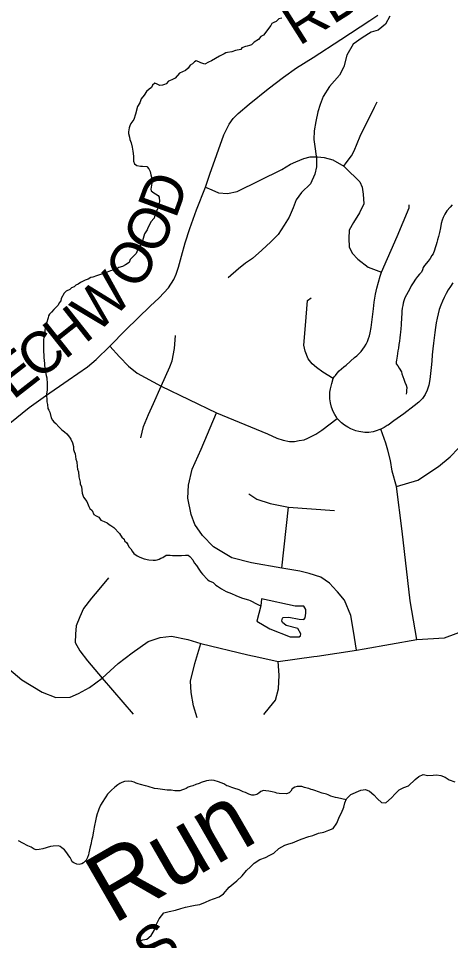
# Model space of a CAD drawing. Extents: x 0 to 34, y 0 to 22.
# Drawn here: x 6.521 to 6.817, y 17.744 to 18.376 of the extents above; entities that cross this region are included whole.
import ezdxf

# ---------------------------------------------------------------- set-up
doc = ezdxf.new("R2010")
doc.units = 0
for name, color, linetype in [('GM_X_County_Road', 7, 'Continuous'), ('GM_X_County_Road_Text', 7, 'Continuous'), ('GM_X_Minor_Lake', 7, 'Continuous'), ('GM_X_Minor_River', 7, 'Continuous'), ('GM_X_Minor_River_Text', 7, 'Continuous'), ('GM_X_Township_Road', 7, 'Continuous'), ('GM_X_Township_Road_Text', 7, 'Continuous')]:
    doc.layers.add(name, color=color, linetype=linetype)

msp = doc.modelspace()

# ---------------------------------------------------------------- linework, layer by layer
at = {"layer": 'GM_X_County_Road'}
msp.add_lwpolyline([(6.51493, 18.09881), (6.52823, 18.10962), (6.5394, 18.11761), (6.55486, 18.12827), (6.5682, 18.13748), (6.57406, 18.1425), (6.58342, 18.15154), (6.59459, 18.16279), (6.61122, 18.17904), (6.61746, 18.18472), (6.62369, 18.19151), (6.62733, 18.19732), (6.62906, 18.20102), (6.63053, 18.20577), (6.63274, 18.21337), (6.63519, 18.22251), (6.63835, 18.23227), (6.64303, 18.24515), (6.6491, 18.26068), (6.65215, 18.2695), (6.66179, 18.29652), (6.66541, 18.30386), (6.66817, 18.30761), (6.67154, 18.31102), (6.67912, 18.31746), (6.69226, 18.32802), (6.70262, 18.33596), (6.71171, 18.34236), (6.72311, 18.34954), (6.74197, 18.36181), (6.76197, 18.37478), (6.76751, 18.37848)], dxfattribs=at)
at = {"layer": 'GM_X_Minor_Lake'}
for points in [[(6.71064, 17.97344), (6.68757, 17.97848), (6.68724, 17.97355)], [(6.68724, 17.97355), (6.68441, 17.96315), (6.69341, 17.95784), (6.70736, 17.95242), (6.71344, 17.95248), (6.7144, 17.95303), (6.71462, 17.95455), (6.71261, 17.9582), (6.70448, 17.96027), (6.70205, 17.96222), (6.70151, 17.96337), (6.70212, 17.96525), (6.7025, 17.96563), (6.70631, 17.96593), (6.7135, 17.96445), (6.71673, 17.96438), (6.71751, 17.96551), (6.71814, 17.96854), (6.71801, 17.9712), (6.71672, 17.97331), (6.71064, 17.97344)]]:
    msp.add_lwpolyline(points, dxfattribs=at)
at = {"layer": 'GM_X_Minor_River'}
for points in [[(6.70166, 18.37648), (6.69956, 18.37597), (6.69761, 18.37412), (6.69608, 18.3734), (6.69473, 18.37287), (6.69413, 18.37137), (6.69236, 18.36933), (6.69059, 18.36691), (6.68902, 18.36486), (6.6871, 18.36377), (6.68553, 18.36192), (6.68263, 18.3601), (6.68069, 18.35825), (6.67934, 18.35772), (6.67781, 18.35719), (6.67667, 18.35703), (6.67418, 18.35614), (6.67339, 18.35503), (6.66976, 18.35436), (6.66727, 18.35348), (6.66422, 18.35299), (6.66307, 18.35264), (6.66192, 18.35191), (6.65884, 18.35047), (6.65325, 18.34721), (6.65133, 18.34631), (6.64863, 18.34486), (6.646, 18.34588), (6.64469, 18.34648), (6.6428, 18.3471), (6.64165, 18.34656), (6.64028, 18.34508), (6.63874, 18.34417), (6.63717, 18.34213), (6.63542, 18.34065), (6.63138, 18.33867), (6.62826, 18.33534), (6.62614, 18.33426), (6.62384, 18.33318), (6.62228, 18.33151), (6.62112, 18.33097), (6.61959, 18.33045), (6.61788, 18.3303), (6.616, 18.3313), (6.6145, 18.33191), (6.61276, 18.33062), (6.61214, 18.32893), (6.6106, 18.32783), (6.60866, 18.32618), (6.60707, 18.32375), (6.60511, 18.32115), (6.60451, 18.31984), (6.60409, 18.31833), (6.60251, 18.3159), (6.60123, 18.31063), (6.6, 18.30706), (6.59784, 18.30427), (6.59723, 18.30257), (6.59682, 18.30126), (6.59637, 18.29861), (6.59634, 18.29729), (6.59703, 18.2948), (6.59718, 18.29328), (6.59808, 18.29098), (6.59876, 18.28812), (6.59926, 18.28526), (6.59974, 18.28183), (6.59969, 18.27993), (6.59985, 18.27841), (6.60037, 18.2765), (6.60205, 18.27551), (6.60451, 18.27507), (6.60584, 18.27503)], [(6.77562, 18.37773), (6.77265, 18.37227), (6.76763, 18.36819), (6.76286, 18.36676), (6.7567, 18.36289), (6.75053, 18.35863), (6.7462, 18.35111), (6.74414, 18.34317), (6.74117, 18.33733), (6.73417, 18.32967), (6.73004, 18.32272), (6.72784, 18.31725), (6.72622, 18.31234), (6.72494, 18.30571), (6.72386, 18.29926), (6.72354, 18.29318), (6.72455, 18.28689), (6.72536, 18.28003), (6.72525, 18.27452), (6.72419, 18.26941), (6.72121, 18.26281), (6.715, 18.25684), (6.71149, 18.25197), (6.70928, 18.2465), (6.70649, 18.24009), (6.70315, 18.23445), (6.69903, 18.22807), (6.69398, 18.22303), (6.68779, 18.21745), (6.68141, 18.21168), (6.67659, 18.20854), (6.67177, 18.20464), (6.6648, 18.1985)], [(6.60584, 18.27503), (6.60887, 18.27476), (6.61035, 18.27321), (6.61125, 18.27129), (6.61176, 18.269), (6.61227, 18.26652), (6.6126, 18.26461), (6.6117, 18.25932), (6.61186, 18.25818), (6.61373, 18.2568), (6.61485, 18.25602), (6.61672, 18.25483), (6.61726, 18.25368), (6.61757, 18.25082), (6.61714, 18.24894), (6.6167, 18.24667), (6.6159, 18.24499), (6.6147, 18.24255), (6.61385, 18.23935), (6.6117, 18.23694), (6.6107, 18.23469), (6.60951, 18.23263), (6.60909, 18.23131), (6.60731, 18.22852), (6.60544, 18.22211), (6.60406, 18.22006), (6.60268, 18.2182), (6.60206, 18.21632), (6.60166, 18.21519), (6.60048, 18.2139), (6.59932, 18.21279), (6.59738, 18.21113), (6.59675, 18.20906), (6.59424, 18.20742), (6.59231, 18.20633), (6.58963, 18.20545), (6.58829, 18.20473), (6.58675, 18.20401), (6.58388, 18.20333), (6.58158, 18.20244), (6.57908, 18.20137), (6.57717, 18.20085), (6.57564, 18.20032), (6.5743, 18.19979), (6.57181, 18.1989), (6.57047, 18.19875), (6.56854, 18.19747), (6.56662, 18.19676), (6.56336, 18.19533), (6.56181, 18.19404), (6.56008, 18.19352), (6.55911, 18.1924), (6.55719, 18.1917), (6.55602, 18.1904), (6.55352, 18.18933), (6.55216, 18.18803), (6.55016, 18.18429), (6.54993, 18.18278), (6.54876, 18.18129), (6.54796, 18.1798), (6.54601, 18.17776), (6.54503, 18.17665), (6.54347, 18.17498), (6.5421, 18.1735), (6.54132, 18.17238), (6.54109, 18.17106), (6.54005, 18.16729), (6.53898, 18.16258), (6.53895, 18.16144), (6.53852, 18.15956), (6.53829, 18.15785), (6.53805, 18.15596), (6.53794, 18.15179), (6.53802, 18.14724), (6.53818, 18.14609), (6.53832, 18.14438), (6.53844, 18.14135), (6.5386, 18.1402), (6.53875, 18.13887), (6.53888, 18.1364), (6.53903, 18.13488), (6.5399, 18.13163), (6.54023, 18.12992), (6.5402, 18.12859), (6.54055, 18.12725), (6.54041, 18.12175), (6.54014, 18.11873), (6.5401, 18.11721), (6.54025, 18.11569), (6.54038, 18.11341), (6.54072, 18.11169), (6.54103, 18.10884), (6.54157, 18.10769), (6.54229, 18.10634), (6.54334, 18.10252), (6.54425, 18.10098), (6.54517, 18.09981), (6.54647, 18.09864), (6.5485, 18.09631), (6.55054, 18.09436), (6.5524, 18.09299)], [(6.81843, 18.2486), (6.81706, 18.24693), (6.81472, 18.24434), (6.81412, 18.24321), (6.81333, 18.24209), (6.81232, 18.23984), (6.81152, 18.23797), (6.81089, 18.23571), (6.81043, 18.23269), (6.80978, 18.22948), (6.80914, 18.22684), (6.80852, 18.22458), (6.8079, 18.2227), (6.80748, 18.221), (6.80686, 18.21912), (6.80625, 18.21743), (6.80542, 18.21498), (6.80463, 18.21368), (6.80345, 18.21181), (6.80207, 18.20995), (6.79952, 18.20698), (6.79854, 18.20549), (6.79812, 18.20398), (6.79732, 18.2023), (6.79614, 18.201), (6.79458, 18.19933), (6.79339, 18.19747), (6.79181, 18.19504), (6.79043, 18.19299), (6.78943, 18.19093), (6.78824, 18.18888), (6.78604, 18.18476), (6.78523, 18.18269), (6.78481, 18.18119), (6.78458, 18.17949), (6.78415, 18.1776), (6.78392, 18.17571), (6.78386, 18.17362), (6.78362, 18.17154), (6.78348, 18.16624), (6.78323, 18.16359), (6.78298, 18.16132), (6.78274, 18.15943), (6.7825, 18.15734), (6.78225, 18.15507), (6.78181, 18.15281), (6.78156, 18.15035), (6.78113, 18.14846), (6.78089, 18.14657), (6.78066, 18.14487), (6.78043, 18.14336), (6.78021, 18.14204), (6.77999, 18.14091), (6.78015, 18.13957), (6.78125, 18.13803), (6.78216, 18.13649), (6.78361, 18.13398), (6.78396, 18.13265), (6.78467, 18.13073), (6.78539, 18.129), (6.78609, 18.1269), (6.7868, 18.12498), (6.78733, 18.12326), (6.78709, 18.12118), (6.78706, 18.12004), (6.78683, 18.11872)], [(6.5524, 18.09299), (6.55407, 18.09142), (6.55572, 18.08929), (6.55664, 18.08794), (6.5579, 18.08525), (6.5586, 18.08277), (6.55854, 18.08068), (6.55908, 18.07953), (6.55961, 18.07781), (6.56028, 18.07419), (6.5608, 18.07228), (6.5611, 18.06904), (6.56143, 18.06733), (6.56195, 18.06542), (6.56225, 18.062), (6.56277, 18.06027), (6.5631, 18.05837), (6.56326, 18.05723), (6.56398, 18.05531), (6.56462, 18.05093), (6.5655, 18.04806), (6.56771, 18.04516), (6.56914, 18.04171), (6.56986, 18.04036), (6.57135, 18.03899), (6.57261, 18.0363), (6.5741, 18.03531), (6.57598, 18.03432), (6.57745, 18.03238), (6.57951, 18.03138), (6.58177, 18.03056), (6.58307, 18.02939), (6.58419, 18.02879), (6.58624, 18.02722), (6.59013, 18.02313), (6.59086, 18.02198), (6.59177, 18.02081), (6.59344, 18.01925), (6.59361, 18.01811), (6.59509, 18.01674), (6.59582, 18.01559), (6.59654, 18.01405), (6.59784, 18.01269), (6.59875, 18.01115), (6.60004, 18.0096), (6.60227, 18.00783), (6.60415, 18.00702), (6.60716, 18.0058), (6.61018, 18.00516), (6.61321, 18.00489), (6.61492, 18.00503), (6.61607, 18.00519), (6.61741, 18.00573), (6.61856, 18.00627), (6.61991, 18.0068), (6.62222, 18.00826), (6.62356, 18.00841), (6.62488, 18.00838), (6.62659, 18.00814), (6.62981, 18.00806), (6.63266, 18.00817), (6.63552, 18.00848), (6.63723, 18.00843), (6.63834, 18.00745), (6.64056, 18.00512), (6.64146, 18.00301), (6.64293, 18.00126), (6.64458, 17.99875), (6.64586, 17.99682), (6.64715, 17.99527), (6.65048, 17.99177), (6.65178, 17.99079), (6.65441, 17.98958), (6.65627, 17.98782), (6.65739, 17.98723), (6.66019, 17.98526), (6.66169, 17.98446), (6.66337, 17.98347), (6.66694, 17.98204), (6.66995, 17.98083), (6.67277, 17.97962), (6.67446, 17.979), (6.67861, 17.97776), (6.67974, 17.97735), (6.68124, 17.97655), (6.6833, 17.97555), (6.68461, 17.97475), (6.68611, 17.97414), (6.68724, 17.97355)], [(6.60245, 17.74361), (6.60607, 17.74469), (6.60892, 17.74521), (6.61181, 17.74763), (6.61396, 17.7512), (6.61536, 17.75498), (6.61733, 17.75913), (6.62063, 17.76325), (6.62425, 17.76414), (6.62862, 17.76501), (6.63225, 17.76609), (6.63549, 17.76717), (6.63968, 17.76805), (6.64215, 17.76839), (6.64538, 17.7689), (6.6492, 17.77055), (6.65207, 17.77183), (6.65474, 17.77273), (6.65856, 17.77419), (6.66163, 17.77622), (6.6655, 17.78072), (6.6682, 17.78314), (6.67071, 17.78519), (6.67437, 17.78854), (6.67728, 17.79229), (6.67998, 17.79472), (6.68268, 17.79733), (6.68652, 17.79974), (6.69034, 17.80119), (6.6934, 17.80266), (6.69608, 17.80413), (6.69955, 17.8073), (6.70357, 17.80951), (6.70644, 17.8106), (6.70891, 17.81113), (6.71216, 17.81259), (6.71483, 17.81369), (6.72018, 17.8155), (6.72284, 17.81621), (6.72667, 17.81786), (6.73028, 17.81855), (6.73372, 17.81982), (6.73678, 17.8211), (6.73931, 17.82467), (6.74109, 17.8292), (6.74247, 17.83164), (6.74405, 17.83561), (6.74487, 17.83863), (6.74605, 17.84127), (6.74895, 17.84426), (6.75583, 17.84718), (6.75906, 17.8477), (6.7617, 17.84651), (6.76468, 17.84399), (6.76729, 17.84129), (6.7699, 17.83877), (6.77293, 17.83872), (6.77679, 17.84207), (6.7793, 17.84469), (6.782, 17.84749), (6.78526, 17.84915), (6.7885, 17.85023), (6.79313, 17.85471), (6.79563, 17.85657), (6.7985, 17.85804), (6.80172, 17.85742), (6.80532, 17.85754), (6.80779, 17.85769), (6.81063, 17.85726), (6.81364, 17.85626), (6.81645, 17.85431), (6.82022, 17.85292)], [(6.74577, 17.84063), (6.73973, 17.84203), (6.7384, 17.84226), (6.7367, 17.84268), (6.7352, 17.8431), (6.73332, 17.8441), (6.73219, 17.84451), (6.72936, 17.84515), (6.72428, 17.84699), (6.72277, 17.84741), (6.72164, 17.84782), (6.72014, 17.84843), (6.719, 17.84865), (6.71712, 17.84907), (6.71523, 17.84969), (6.71201, 17.84978), (6.71048, 17.84944), (6.70874, 17.84816), (6.70775, 17.84666), (6.70658, 17.84537), (6.70466, 17.84485), (6.69973, 17.84498), (6.69822, 17.84521), (6.69709, 17.84561), (6.69501, 17.84605), (6.69388, 17.84627), (6.69256, 17.84668), (6.69066, 17.84692), (6.68896, 17.84697), (6.68704, 17.84645), (6.68569, 17.84534), (6.68433, 17.84443), (6.68261, 17.84391), (6.6809, 17.84395), (6.67902, 17.84457), (6.67658, 17.84558), (6.67507, 17.84619), (6.67226, 17.84759), (6.66868, 17.84863), (6.66736, 17.84905), (6.66492, 17.85006), (6.66378, 17.85028), (6.66173, 17.85166), (6.65816, 17.85308), (6.65514, 17.85392), (6.65306, 17.85416), (6.64982, 17.85368), (6.64618, 17.85245), (6.64483, 17.85191), (6.64254, 17.85122), (6.64042, 17.85032), (6.6387, 17.8498), (6.63736, 17.84927), (6.63601, 17.84854), (6.63467, 17.84801), (6.63332, 17.84747), (6.6316, 17.84676), (6.62818, 17.84685), (6.62553, 17.8473), (6.62288, 17.84737), (6.61644, 17.84811), (6.61417, 17.84854), (6.60984, 17.8498), (6.60795, 17.85022), (6.60455, 17.85107), (6.60286, 17.85169), (6.60154, 17.8521), (6.60022, 17.8527), (6.59852, 17.85313), (6.59626, 17.85357), (6.59359, 17.85326), (6.59167, 17.85255), (6.59033, 17.85182), (6.58897, 17.85091), (6.58685, 17.84945), (6.58432, 17.84705), (6.58197, 17.84445), (6.58079, 17.84278), (6.5798, 17.84129), (6.57862, 17.83942), (6.57722, 17.83699), (6.57602, 17.83436), (6.57541, 17.83286), (6.57479, 17.83098), (6.57416, 17.82853), (6.57372, 17.82627), (6.57307, 17.82306), (6.57285, 17.82193), (6.5724, 17.81909), (6.57218, 17.81796), (6.57154, 17.81513), (6.57113, 17.81381), (6.57046, 17.81004), (6.57004, 17.80853), (6.56918, 17.80438), (6.56876, 17.80287), (6.56815, 17.80118), (6.56734, 17.79931), (6.56539, 17.79746), (6.56424, 17.79673), (6.56252, 17.7964)], [(6.56252, 17.7964), (6.56082, 17.79663), (6.55875, 17.79745), (6.55763, 17.79823), (6.55709, 17.79939), (6.55618, 17.80112), (6.55545, 17.80227), (6.55399, 17.8044), (6.55233, 17.80634), (6.55065, 17.80771), (6.54935, 17.80869), (6.54822, 17.8091), (6.54461, 17.80901), (6.5427, 17.80868), (6.53753, 17.80711), (6.53505, 17.8066), (6.53296, 17.80647), (6.53164, 17.80688), (6.52959, 17.80826), (6.52733, 17.80908), (6.52377, 17.81088), (6.52077, 17.81248)]]:
    msp.add_lwpolyline(points, dxfattribs=at)
at = {"layer": 'GM_X_Township_Road'}
msp.add_line((6.7015, 17.99956), (6.70606, 18.0412), dxfattribs=at)
for points in [[(6.74411, 18.27502), (6.74564, 18.27725), (6.7494, 18.28217), (6.75128, 18.28554), (6.75541, 18.29546), (6.76513, 18.31537), (6.76702, 18.319)], [(6.6491, 18.26068), (6.65353, 18.25875), (6.65813, 18.25681), (6.66428, 18.25619), (6.67083, 18.25753), (6.70151, 18.27274), (6.70762, 18.27629), (6.71111, 18.27804), (6.71671, 18.28031), (6.72108, 18.28136), (6.72606, 18.28136), (6.73052, 18.28101), (6.73655, 18.27926), (6.74411, 18.27502), (6.74818, 18.27096), (6.75185, 18.26746), (6.75499, 18.26432), (6.75665, 18.26064), (6.75744, 18.25575), (6.75779, 18.24928), (6.75491, 18.24299), (6.75066, 18.23639), (6.74774, 18.2311), (6.74751, 18.22536), (6.74779, 18.21963), (6.7498, 18.21533), (6.75367, 18.21117), (6.76083, 18.20573), (6.77003, 18.20232)], [(6.81904, 18.19496), (6.81737, 18.19263), (6.8158, 18.1902), (6.81435, 18.18769), (6.81369, 18.18638), (6.81302, 18.18508), (6.81178, 18.18241), (6.81066, 18.17964), (6.80966, 18.17677), (6.80884, 18.17379), (6.80814, 18.17078), (6.80756, 18.16762), (6.80704, 18.16439), (6.80655, 18.16101), (6.80609, 18.15744), (6.80566, 18.15369), (6.80524, 18.14975), (6.80482, 18.14564), (6.80444, 18.14137), (6.80403, 18.13703), (6.80358, 18.13279), (6.80308, 18.12875), (6.8024, 18.125), (6.80137, 18.12155), (6.79994, 18.11844), (6.79856, 18.11642), (6.79806, 18.11568), (6.79569, 18.11325), (6.79249, 18.11078), (6.78534, 18.10526), (6.77845, 18.10038), (6.77448, 18.09757), (6.77387, 18.09714), (6.7718, 18.09591), (6.76952, 18.09466), (6.76564, 18.09339), (6.76422, 18.09299), (6.76136, 18.0925), (6.7586, 18.0925), (6.75443, 18.09304), (6.7524, 18.09367), (6.75122, 18.09404), (6.74886, 18.09498), (6.74682, 18.09606), (6.74458, 18.09749), (6.74259, 18.09905), (6.73958, 18.10203), (6.73901, 18.10293), (6.73788, 18.10483), (6.73687, 18.10678), (6.73572, 18.10984), (6.73493, 18.11273), (6.73447, 18.11549), (6.73441, 18.11812), (6.73454, 18.12016), (6.73487, 18.12227), (6.73585, 18.12595), (6.7369, 18.12957), (6.73756, 18.13062), (6.73829, 18.13147), (6.73957, 18.13311), (6.74096, 18.13467), (6.74245, 18.13612), (6.74404, 18.13747), (6.74572, 18.13871), (6.75137, 18.14377), (6.75299, 18.14506), (6.7545, 18.14646), (6.75591, 18.14796), (6.7572, 18.14956), (6.75839, 18.15126), (6.75944, 18.15303), (6.76036, 18.15487), (6.76114, 18.15678), (6.76179, 18.15874), (6.76229, 18.16074), (6.76277, 18.16453), (6.76439, 18.17724), (6.76498, 18.18172), (6.76584, 18.18717), (6.76676, 18.19145), (6.76781, 18.19546), (6.769, 18.19954), (6.77003, 18.20232), (6.7808, 18.22668), (6.78903, 18.24645), (6.78897, 18.24851)], [(6.7369, 18.12957), (6.7297, 18.13387), (6.72525, 18.13694), (6.72233, 18.1394), (6.71972, 18.14293), (6.71757, 18.14815), (6.71665, 18.1523), (6.7178, 18.1659), (6.71915, 18.18285), (6.72172, 18.1847)], [(6.60471, 18.08871), (6.60673, 18.09652), (6.6101, 18.10488), (6.61347, 18.11229), (6.61886, 18.12428), (6.62479, 18.13748), (6.6264, 18.14166), (6.62789, 18.15002), (6.62869, 18.15891)], [(6.75799, 17.94414), (6.79427, 17.95061), (6.81315, 17.95168), (6.83116, 17.95844), (6.84818, 17.97135), (6.85869, 17.98267), (6.86381, 17.9921), (6.87163, 18.0115), (6.87506, 18.02035), (6.88458, 18.0461), (6.89031, 18.06087), (6.89605, 18.07661), (6.89861, 18.08284), (6.89945, 18.08851), (6.89627, 18.09883), (6.87848, 18.15666)], [(6.58342, 18.15154), (6.59016, 18.14422), (6.59636, 18.13802), (6.60228, 18.13304), (6.61886, 18.12428), (6.65663, 18.10584), (6.6917, 18.09164), (6.69807, 18.08849), (6.70252, 18.08711), (6.70675, 18.08634), (6.71028, 18.08626), (6.7135, 18.08696), (6.71688, 18.08749), (6.71934, 18.08849), (6.72479, 18.09126), (6.72909, 18.09394), (6.73958, 18.10203)], [(6.73971, 17.98322), (6.73941, 17.98358), (6.73439, 17.98923), (6.72827, 17.99321), (6.72043, 17.99588), (6.7139, 17.99747), (6.7015, 17.99956), (6.68068, 18.00304), (6.66724, 18.0066), (6.65456, 18.01399), (6.64717, 18.02191), (6.64189, 18.02931), (6.63925, 18.03618), (6.63713, 18.04753), (6.6374, 18.05625), (6.64004, 18.06734), (6.64611, 18.08107), (6.65663, 18.10584)], [(6.78024, 18.05538), (6.79489, 18.05977), (6.80904, 18.06905), (6.8171, 18.07588), (6.82857, 18.0876), (6.83748, 18.10584)], [(6.79427, 17.95061), (6.78971, 17.97701), (6.78405, 18.02471), (6.78024, 18.05538), (6.77731, 18.06589), (6.7761, 18.07321), (6.77439, 18.08037), (6.77304, 18.08508), (6.76952, 18.09466)], [(6.67886, 18.05044), (6.68441, 18.04674), (6.69365, 18.04384), (6.70606, 18.0412), (6.7376, 18.03893)], [(6.46583, 17.9965), (6.46989, 17.99402), (6.48013, 17.98775), (6.48737, 17.9808), (6.49353, 17.96981), (6.50103, 17.95381), (6.50686, 17.94065), (6.51419, 17.93049), (6.52319, 17.92299), (6.53718, 17.9145), (6.54635, 17.91083), (6.55634, 17.911), (6.56211, 17.91348), (6.5695, 17.91766), (6.57817, 17.92416), (6.58934, 17.93412), (6.59891, 17.94153), (6.60973, 17.9491), (6.61807, 17.95204), (6.62595, 17.95296), (6.63707, 17.95065), (6.64603, 17.94787), (6.67816, 17.94014), (6.68571, 17.93846)], [(6.5825, 17.9928), (6.576, 17.9848), (6.571, 17.9788), (6.56534, 17.97181), (6.56284, 17.96614), (6.56051, 17.95998), (6.55984, 17.95431), (6.55982, 17.94853), (6.5629, 17.94269), (6.56826, 17.93601), (6.57817, 17.92416), (6.59955, 17.8993)], [(6.75281, 17.94322), (6.7507, 17.95628), (6.74882, 17.96695), (6.74462, 17.97755), (6.73971, 17.98322)], [(6.6434, 17.89689), (6.64093, 17.90507), (6.63923, 17.91419), (6.63877, 17.92207), (6.64186, 17.93412), (6.64603, 17.94787)], [(6.72346, 17.93888), (6.7259, 17.93921), (6.75281, 17.94322), (6.75799, 17.94414)], [(6.68571, 17.93846), (6.69902, 17.93551), (6.72346, 17.93888)], [(6.68913, 17.8992), (6.693, 17.90384), (6.69732, 17.90909), (6.69918, 17.91666), (6.69979, 17.92608), (6.69902, 17.93551)]]:
    msp.add_lwpolyline(points, dxfattribs=at)

# ---------------------------------------------------------------- texts
at = {"layer": 'GM_X_County_Road_Text'}
for s, height, rotation, p in [('RD', 0.028409, 32.36225, (6.7134, 18.35704)), ('D', 0.02841, 69.91079, (6.62868, 18.23826)), ('O', 0.02841, 65.00432, (6.61709, 18.21315)), ('O', 0.02841, 59.95005, (6.60331, 18.18908)), ('W', 0.02841, 44.00322, (6.57433, 18.15943)), ('H', 0.02841, 38.46554, (6.5525, 18.1419)), ('C', 0.02841, 37.77776, (6.53377, 18.12738)), ('E', 0.02841, 37.91821, (6.51702, 18.11433))]:
    msp.add_text(s, height=height, rotation=rotation, dxfattribs=at).set_placement(p)
at = {"layer": 'GM_X_Minor_River_Text'}
msp.add_text('Run', height=0.047351, rotation=30.0038, dxfattribs=at).set_placement((6.58586, 17.755))
at = {"layer": 'GM_X_Township_Road_Text'}
msp.add_text('S', height=0.02841, rotation=39.59263, dxfattribs=at).set_placement((6.61451, 17.72201))

doc.saveas('drawing.dxf')
